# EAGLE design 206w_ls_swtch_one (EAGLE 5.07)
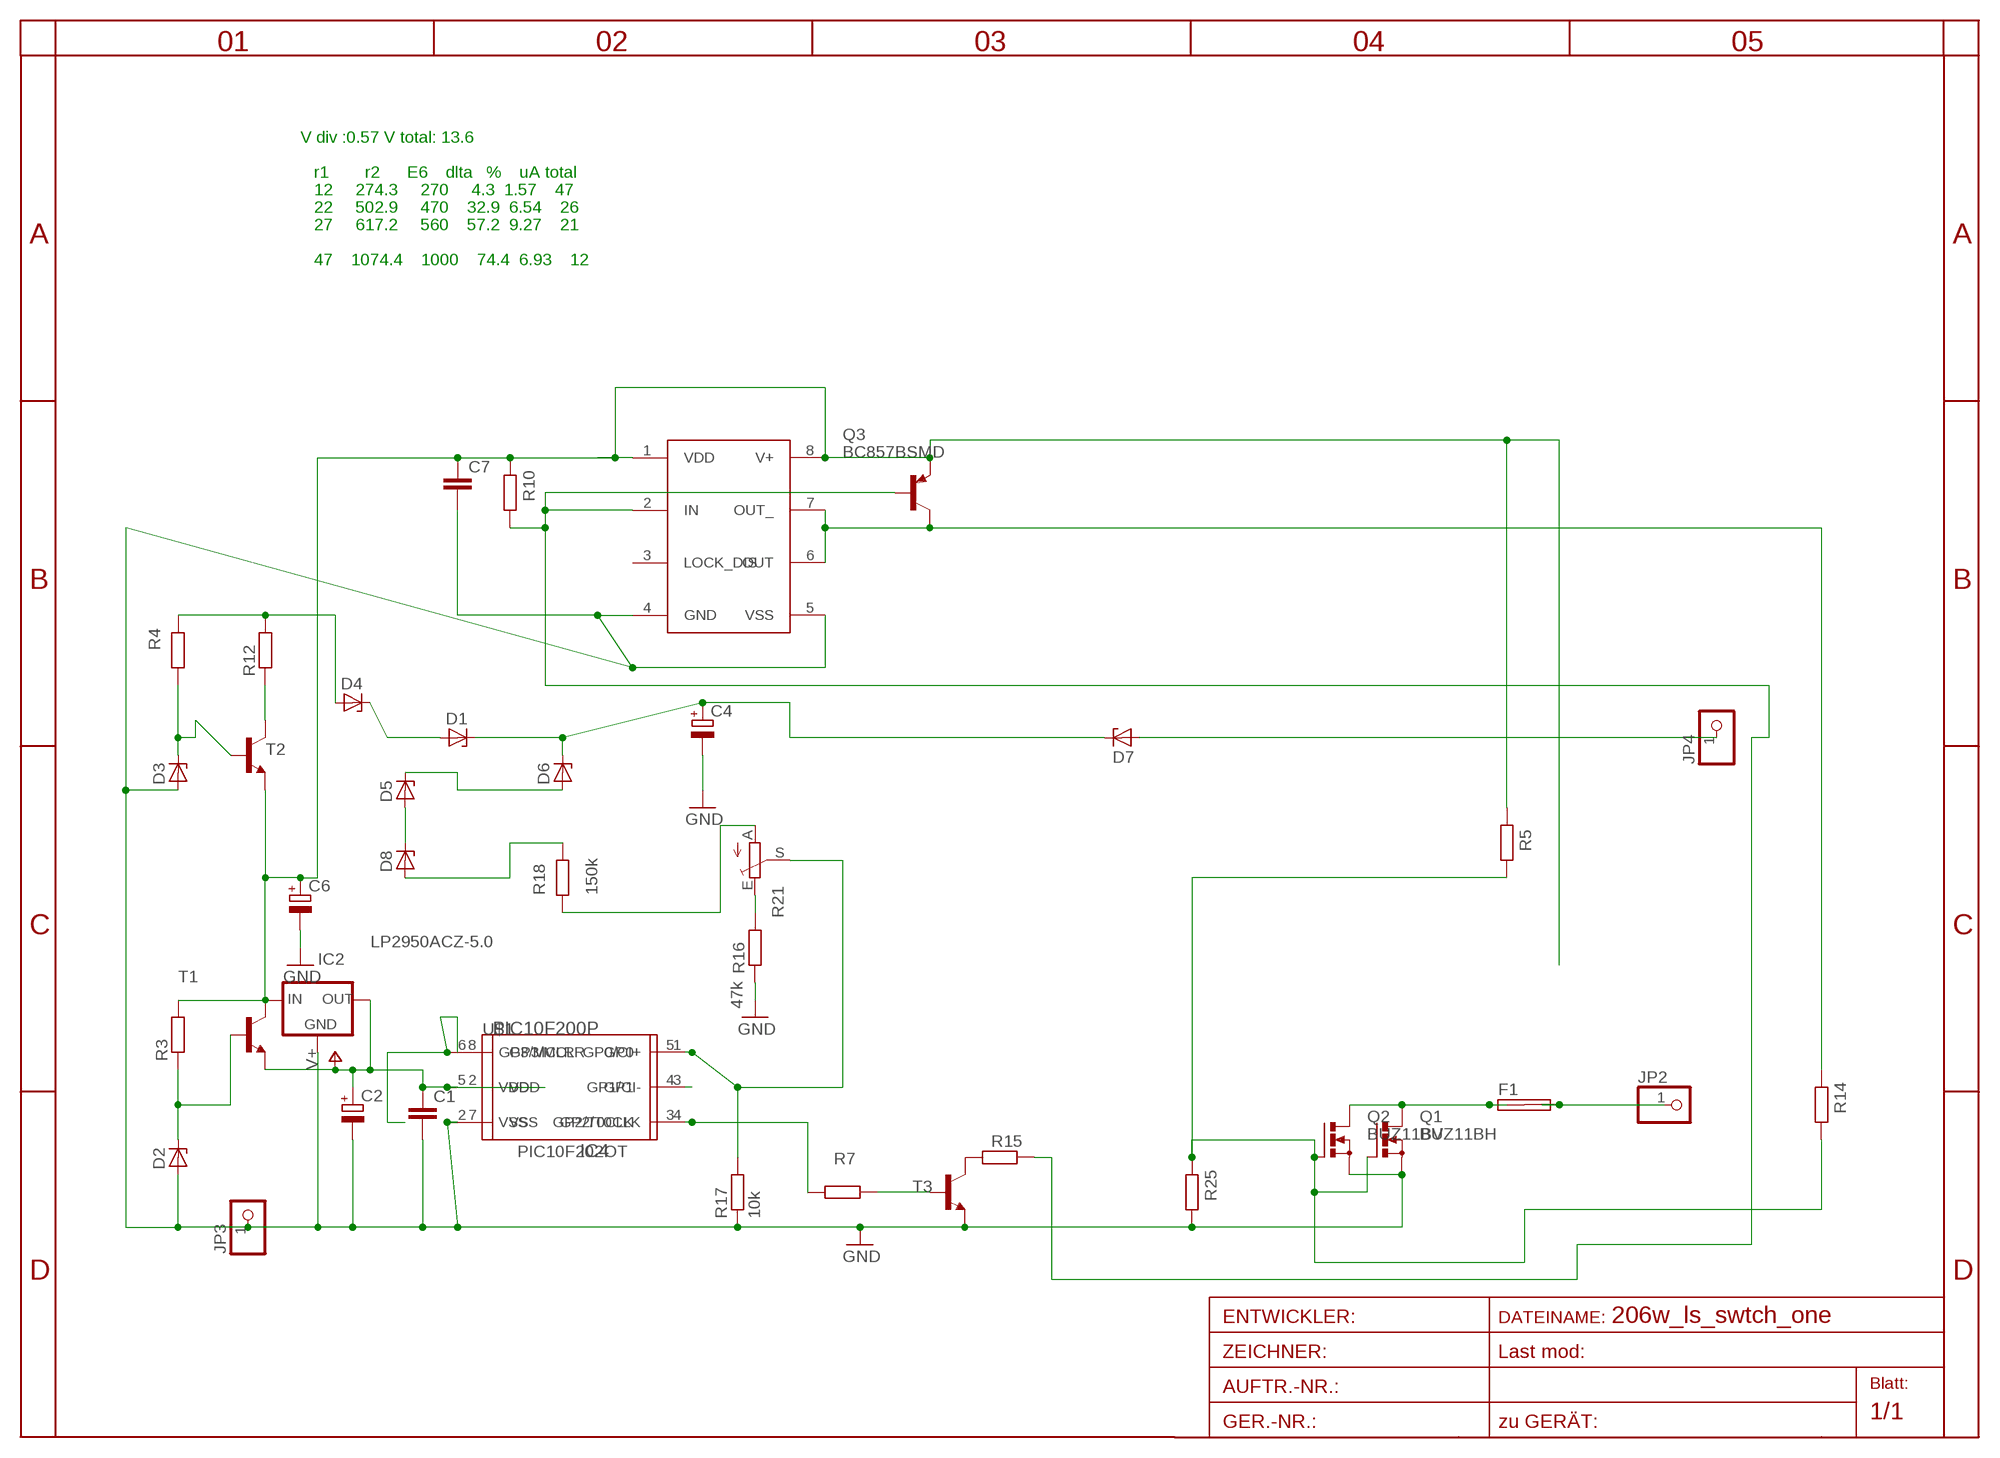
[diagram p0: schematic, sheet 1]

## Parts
C1  C-EUC1206  [C1206]
C2  CPOL-EUSANYO_SMD_E12  [SANYO-OSCON_SMD_E12]
C4  CPOL-EUE5-8.5  [E5-8,5]
C6  CPOL-EUSANYO_SMD_E12  [SANYO-OSCON_SMD_E12]
C7  C-EUC1206  [C1206]
D1  ZENER-DIODESMB  [SMB]
D2  ZENER-DIODESOD80C  [SOD80C]
D3  ZENER-DIODESMB  [SMB]
D4  ZENER-DIODESMB  [SMB]
D5  ZENER-DIODESMB  [SMB]
D6  ZENER-DIODESMB  [SMB]
D7  ZENER-DIODESMB  [SMB]
D8  ZENER-DIODESMB  [SMB]
F1  SHK20L7MM5  [7MM5]
IC2  LP2950ACZ-5.0  [TO92]
IC3  TC4432X  [SO-08]
IC4  PIC10F200P  [DIL8]
JP2  PINHD-1X11MM6  [1X1MM8]
JP3  PINHD-1X11MM6  [1X1MM8]
JP4  PINHD-1X11MM6  [1X1MM8]
Q1  BUZ11BH  [TO220BH]
Q2  BUZ11BV  [TO220BV]
Q3  BC857BSMD  [SOT23-BEC]
R3  R-EU_R0805  [R0805]
R4  R-EU_R0805  [R0805]
R5  R-EU_R0805  [R0805]
R7  R-EU_R0805  [R0805]
R10  R-EU_R0805  [R0805]
R12  R-EU_R0805  [R0805]
R14  R-EU_R0805  [R0805]
R15  R-EU_R0805  [R0805]
R16  47k  R-EU_R0805  [R0805]
R17  10k  R-EU_R0805  [R0805]
R18  150k  R-EU_R1206  [R1206]
R21  TRIM_EU-CA6V  [CA6V]
R25  R-EU_R0805  [R0805]
T1  BC846BLT1-NPN-SOT23-BEC  [SOT23-BEC]
T2  BC846BLT1-NPN-SOT23-BEC  [SOT23-BEC]
T3  BC846BLT1-NPN-SOT23-BEC  [SOT23-BEC]
U$1  PIC10F202OT  [SOT23-6]

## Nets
BB: IC3.2(IN) Q3.B R10.1 R15.2
GND: C1.2 C2.- C4.- C6.- C7.2 D2.A D3.A IC2.2(GND) IC3.4(GND) IC3.5(VSS) IC4.7(VSS) JP3.1 Q1.S Q2.S R16.1 R17.1 R25.1 T3.E U$1.2(VSS)
HOTSPOT: F1.1A F1.1B Q1.D Q2.D
N$1: IC4.5(GP0) R17.2 R21.S U$1.1(GP0/CI+)
N$2: IC4.8(GP3/MCLR) U$1.6(GP3/MCLR)
N$3: Q1.G Q2.G R5.1 R14.1 R25.2
N$4: R18.1 R21.A
N$5: R16.2 R21.E
N$6: D2.C R3.1 T1.B
N$7: D7.A JP4.1
N$9: IC4.3(GP2/T0CLK) R7.1 U$1.4(GP2/T0CLK)
N$10: D5.C D6.A
N$11: IC3.6(OUT) IC3.7(OUT_) Q3.C R14.2
N$12: D3.C R4.1 T2.B
N$16: R12.1 T2.C
N$17: D5.A D8.C
N$18: D1.A D4.C
N$19: D8.A R18.2
N$21: D4.A R4.2 R12.2
N$25: IC4.4(GP1) U$1.3(GP1/CI-)
N$26: R7.2 T3.B
N$31: R15.1 T3.C
OUT-: F1.2A F1.2B JP2.1
V60: C4.+ D1.C D6.C D7.C
V+: C1.1 C2.+ IC2.1(OUT) IC4.2(VDD) T1.E U$1.5(VDD)
VCC: C6.+ C7.1 IC2.3(IN) IC3.1(VDD) IC3.8(V+) Q3.E R3.2 R5.2 R10.2 T1.C T2.E
Unconnected: IC3.3(LOCK_DIS)

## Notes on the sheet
- V div :0.57 V total: 13.6
- r1        r2      E6    dlta   %    uA total
- 12     274.3     270     4.3  1.57    47
- 22     502.9     470    32.9  6.54    26
- 27     617.2     560    57.2  9.27    21
- 47    1074.4    1000    74.4  6.93    12

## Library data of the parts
C1 C7 = rcl:C-EU: CAPACITOR, European symbol
C2 C4 C6 = rcl:CPOL-EU: POLARIZED CAPACITOR, European symbol
D1-D8 = diode-1:ZENER-DIODE: Z-Diode
F1 = fuse:SHK20L: FUSE HOLDER 5 x 20 mm, SH contact, SHH1 Schukat, E1073 Buerklin
IC2 = v-reg:LP2950?*: Source: http://cache.national.com/ds/LP/LP2950.pdf
IC3 = microchip:TC4432
IC4 = microchip-5:PIC10F20*: uPC nW 0,25/0,5k Program Flash memory
JP2-JP4 = pinhead:PINHD-1X1: PIN HEADER
Q1 Q2 = transistor-power:BUZ11: N-CHANNEL MOS FET
Q3 = transistor-pnp:BC857*: PNP Transistror
R3-R5 R10 R12 R14-R16 R25 = rcl:R-EU_: RESISTOR, European symbol
R7 R17 R18 = rcl-2:R-EU_: RESISTOR, European symbol
R21 = pot:TRIM_EU-: POTENTIOMETER
T1-T3 = transistor-neu-to92:*-NPN-: NPN Transistror
U$1 = microchip-5:PIC10F2*: uPC nW 0,25/0,5k Program Flash memory Comparator

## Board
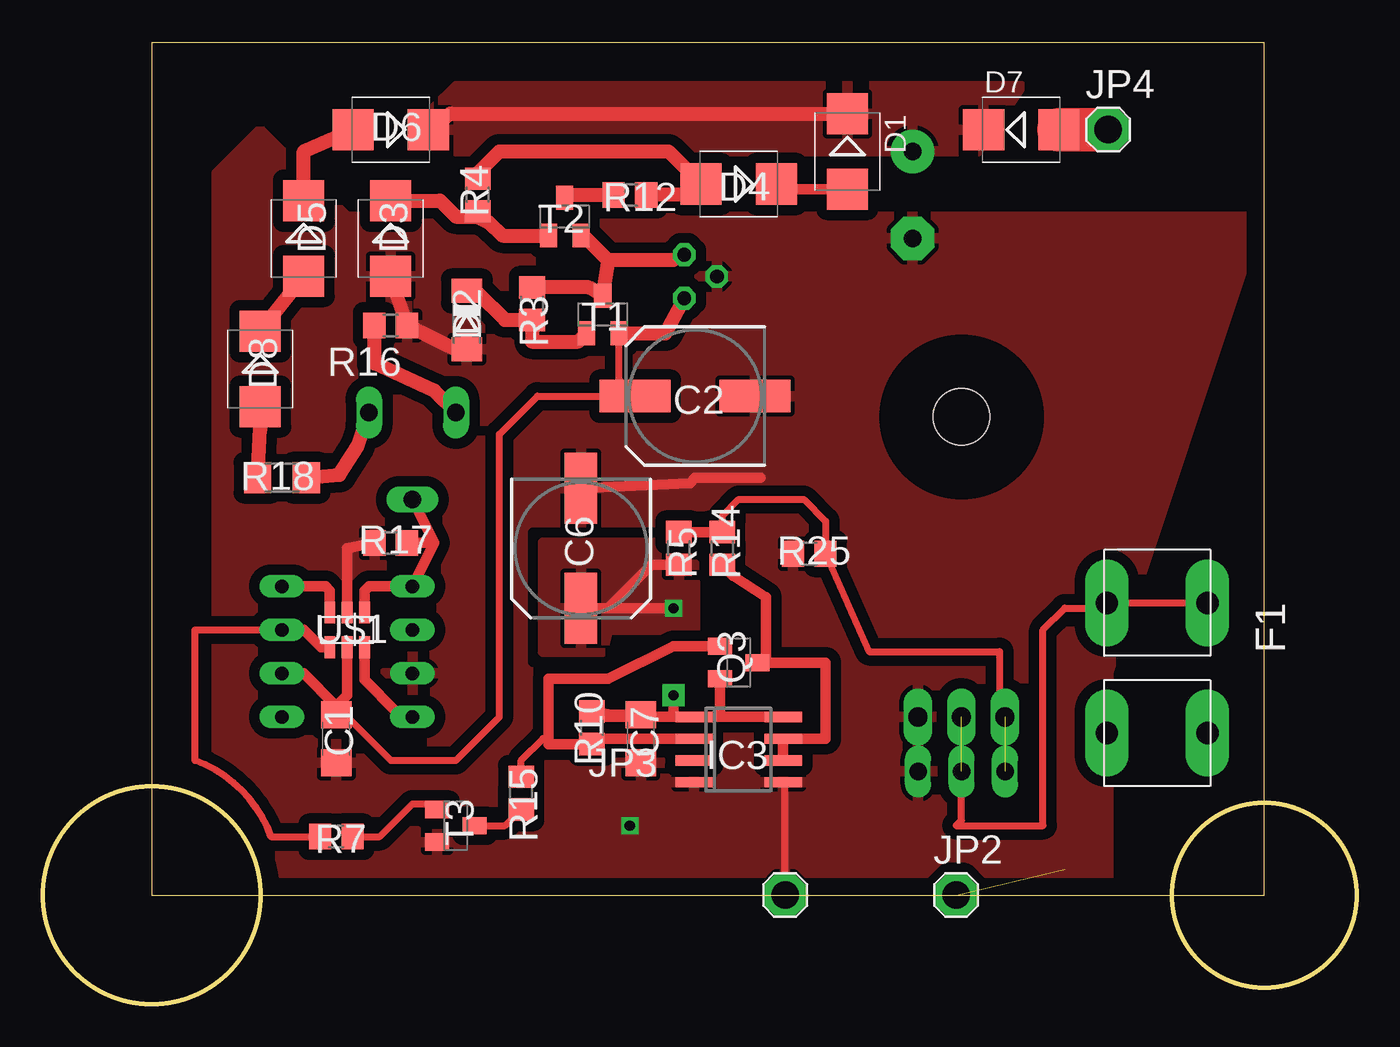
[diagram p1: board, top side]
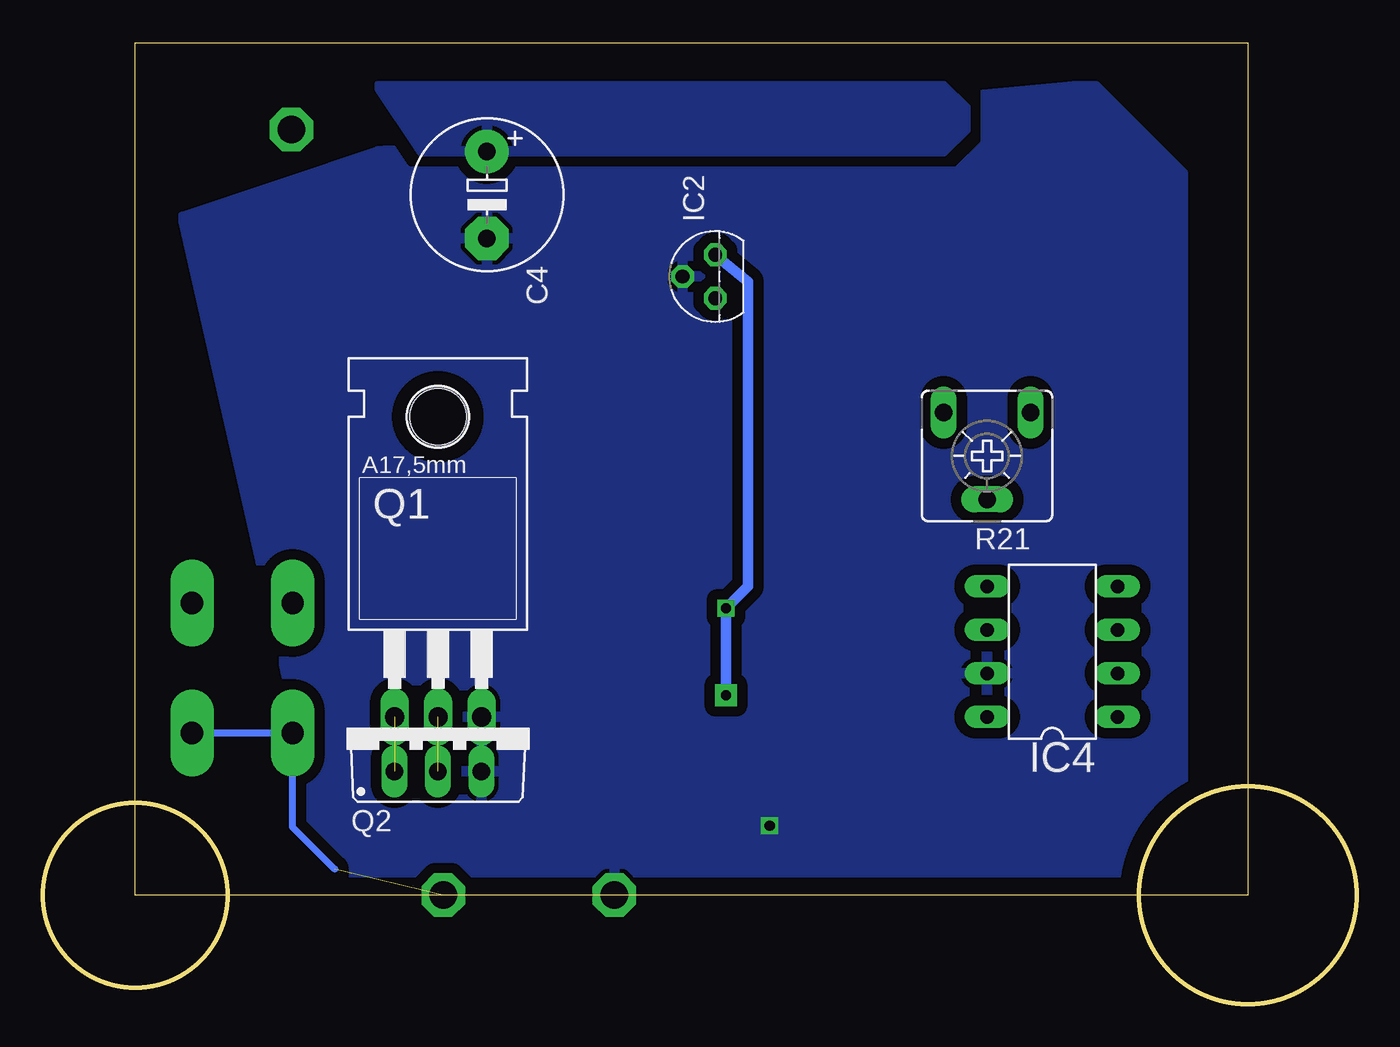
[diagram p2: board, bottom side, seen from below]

Size 76.74 x 56.11 mm. Coordinates in mm from the lower left corner, seen from the top.
Outline: 6.35,6.35 71.35,6.35 71.35,56.11 6.35,56.11 6.35,6.35
Outline: circle at 71.35,6.35 radius 5.39
Outline: circle at 6.35,6.35 radius 6.35
Copper layers (1*16): Top 0.035mm / dielectric 1.5mm / Bottom 0.035mm
Design rules "default": minimum track width 10mil, minimum drill 24mil, track to track 8mil, track to pad 8mil, pad to pad 8mil, via to via 8mil, smd to smd 8mil, copper to edge 40mil, drill to drill 8mil, minimum pad ring 10mil, minimum via ring 8mil, stop-mask expansion 4mil, vias tented up to drill 0mil, thermal gap 10mil

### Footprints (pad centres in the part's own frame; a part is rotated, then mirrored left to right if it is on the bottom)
C1206 = smd 1.6 x 1.8: 1 -1.4,0; 2 1.4,0
SANYO-OSCON_SMD_E12 = smd 4.15 x 1.9: + 3.5,0; - -3.5,0
E5-8,5 = drill 1.016 pad 2.54 round: + -2.54,0 | drill 1.016 pad 2.54 octagon: - 2.54,0
SMB = smd 2.4 x 2.4: A 2.2,0; C -2.2,0
SOD80C = smd 1.4 x 1.8: A 1.7,0; C -1.7,0
7MM5 = drill 1.3 pad 2.54 long: 1A -3.8,2.94; 1B -3.8,-2.94; 2A 3.8,2.94; 2B 3.8,-2.94
TO92 = drill 0.813 octagon: 1 -1.27,0; 2 0,1.905; 3 1.27,0
SO-08 = smd 0.6 x 2.2: 1 -1.905,-2.6; 2 -0.635,-2.6; 3 0.635,-2.6; 4 1.905,-2.6; 5 1.905,2.6; 6 0.635,2.6; 7 -0.635,2.6; 8 -1.905,2.6
DIL8 = drill 0.8 long: 1 -3.81,-3.81; 2 -1.27,-3.81; 3 1.27,-3.81; 4 3.81,-3.81; 5 3.81,3.81; 6 1.27,3.81; 7 -1.27,3.81; 8 -3.81,3.81
1X1MM8 = drill 1.6 pad 2.54 octagon: 1 0,0
TO220BH = drill 1.118 long: D 0,-6.35; G -2.54,-6.35; S 2.54,-6.35 | hole 3.302: 0,11.176
TO220BV = drill 1.016 long: D 0,-2.54; G -2.54,-2.54; S 2.54,-2.54
SOT23-BEC = smd 1 x 1.4: B -0.95,-1.1; C 0,1.1; E 0.95,-1.1
R0805 = smd 1.3 x 1.5: 1 -0.95,0; 2 0.95,0
R1206 = smd 1.6 x 1.803: 1 -1.422,0; 2 1.422,0
CA6V = drill 1.016 long: A -2.54,-2.54; E 2.54,-2.54; S 0,2.54
SOT23-6 = smd 0.635 x 1.27: 1 -1.016,-1.016; 2 0,-1.016; 3 1.016,-1.016; 4 1.016,1.016; 5 0,1.016; 6 -1.016,1.016

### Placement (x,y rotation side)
C1  17.14,15.48 270 top
C2  38.1,35.48 180 top
C4  50.8,47.23 270 bottom
C6  31.43,26.59 270 top
C7  34.92,15.48 270 top
D1  46.99,49.77 270 top
D2  24.77,39.93 270 top
D3  20.32,44.69 270 top
D4  40.64,47.87 180 top
D5  15.24,44.69 270 top
D6  20.32,51.04 180 top
D7  57.15,51.04 0 top
D8  12.7,37.07 270 top
F1  65.09,19.61 270 top
IC2  37.46,42.47 90 bottom
IC3  40.64,14.85 270 top
IC4  17.78,20.56 90 bottom
JP2  53.35,6.35 0 top
JP3  43.35,6.35 0 top
JP4  62.23,51.04 0 top
Q1  53.66,23.1 0 bottom
Q2  53.66,16.12 0 bottom
Q3  40.64,19.92 270 top
R3  28.58,40.88 90 top
R4  25.4,47.23 90 top
R5  37.15,26.59 270 top
R7  17.14,9.76 0 top
R10  32.07,16.12 90 top
R12  34.29,47.23 0 top
R14  39.69,26.59 270 top
R15  27.94,12.3 90 top
R16  20.32,39.61 180 top
R17  20.32,26.91 0 top
R18  13.97,30.72 180 top
R21  21.59,31.99 180 bottom
R25  44.77,26.27 0 top
T1  32.7,40.25 0 top
T2  30.48,45.96 0 top
T3  24.13,10.4 270 top
U$1  17.78,21.83 180 top

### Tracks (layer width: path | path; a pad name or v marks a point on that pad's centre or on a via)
BB
  Top 0.406: R15.2 27.94,14.21 29.21,15.48 29.53,15.48
  Top 0.61: Q3.B 36.83,20.88 33.02,18.97 29.53,18.97 29.53,15.48 29.53,15.16 R10.1 32.38,15.48 IC3.2
GND  (via drill 0.6)
  Top 0.406: JP3.1 43.35,12.83 IC3.5
  Top 0.61: C6.- 37.79,30.41 38.1,30.72 41.91,30.72 | U$1.2 17.78,26.59 R17.1
  Top 0.813: D3.A R16.1 24.56,38.02 D2.A
  other vias: 34.29,10.4
  pour Top (isolate 0.61, rank 3): 17.78,45.96 12.7,51.04 10.16,48.5 10.16,12.94 13.97,6.35 62.23,6.35 62.23,19.29 71.12,45.96
  pour Bottom (isolate 0.61, rank 3): 16.51,53.58 15.24,53.58 10.16,48.5 10.16,12.94 13.97,6.35 62.23,6.35 62.23,18.02 68.58,45.96 57.15,49.77
HOTSPOT  (1 unrouted)
  Top 0.406: Q2.D 53.66,10.72 53.34,10.4 58.42,10.4 58.42,21.83 59.69,23.1 61.84,23.1 F1.1B F1.1A
N$1
  Top 0.61: U$1.1 18.8,24.12 19.05,24.37 IC4.5 22.86,26.91 | 22.86,26.91 R21.S | 22.86,26.91 R17.2
N$2
  Top 0.61: U$1.6 18.8,18.91 20.64,17.07 21.27,17.07 IC4.8
N$3  (1 unrouted)
  Top 0.406: R14.1 39.69,28.5 40.64,29.45 44.45,29.45 45.72,28.18 R25.2 48.26,20.56 55.88,20.56 55.88,17.07 Q1.G
  Top 0.61: R5.1 R14.1
N$4
  Top 0.813: R18.1 17.31,30.88 18.41,32.62 R21.A
N$5
  Top 0.813: R16.2 19.37,37.39 22.86,35.8 R21.E
N$6
  Top 0.813: D2.C 24.88,41.52 25.4,41.52 26.98,39.93 R3.1 28.58,38.66 31.27,38.66 T1.B
N$7
  Top 2.54: D7.A JP4.1
N$9
  Top 0.406: R7.1 13.34,9.76 arc51 8.89,14.21 8.89,21.83 IC4.3
  Top 0.61: U$1.4 16.26,20.81 15.24,21.83 IC4.3
N$10
  Top 0.813: D6.A 15.24,49.77 D5.C
N$11
  Top 0.61: 42.23,19.92 Q3.C | 42.23,19.92 42.23,23.73 40.32,25.01 R14.2 | 42.23,19.92 45.72,19.92 45.72,15.48 IC3.7 IC3.6
N$12
  Top 0.813: D3.C 23.2,46.89 24.13,45.96 25.4,45.96 | T2.B 26.84,44.86 26.03,45.64 25.4,45.96 | 25.4,45.96 R4.1
N$16
  Top 0.813: R12.1 30.48,47.23 T2.C
N$17
  Top 0.813: D8.C D5.A
N$18
  Top 0.61: D1.A 43.13,47.57 D4.C
N$19
  Top 0.813: D8.A 12.7,33.58 R18.2
N$21
  Top 0.813: R4.2 25.4,48.5 26.67,49.77 36.53,49.77 D4.A 37.8,47.23 R12.2
N$25
  Top 0.61: U$1.3 16.76,24.12 16.51,24.37 IC4.4
N$26
  Top 0.406: R7.2 19.69,9.76 21.59,11.67 22.71,11.67 T3.B
N$31
  Top 0.406: T3.C 26.98,10.4 R15.1
OUT-  (1 unrouted)
  Bottom 0.406: F1.2A F1.2B 62.15,10.32 59.69,7.86
V60
  Top 0.813: D1.C 23.79,51.97 D6.C
  pour Top (isolate 0.61): 57.15,53.58 24.13,53.58 22.86,52.31 22.86,51.04 24.13,49.77 54.61,49.77
  pour Bottom (isolate 0.61): 57.15,53.58 24.13,53.58 22.86,52.31 22.86,51.04 24.13,49.77 54.61,49.77
V+
  Top 0.406: T1.E 33.65,36.44 34.29,35.8 34.29,35.79 C2.+ 28.89,35.48 26.67,33.26 26.67,16.75 24.13,14.21 20.32,14.21 17.78,16.75 17.27,16.75 C1.1
  Top 0.61: 17.14,17.38 C1.1 | 17.14,17.38 15.24,19.29 IC4.2 | U$1.5 17.78,18.02 17.14,17.38
  Top 0.813: T1.E 36.37,39.15 IC2.1
VCC  (via drill 0.6, 0.6 pad 1.27)
  Top 0.61: Q3.E 39.54,16.9 39.69,16.75 | 41.27,16.75 IC3.8 39.69,16.75 | 39.69,16.75 IC3.1 36.83,16.75 | 36.83,16.75 31.88,16.75 C7.1 33.2,16.88 R10.2 | R5.2 35.56,25.64 33.02,23.1 | 32.06,23.1 C6.+ 31.75,23.1 32.06,23.1 | v36.83,23.1 33.02,23.1 | 36.83,16.75 v36.83,18.02 | 33.02,23.1 32.06,23.1 | IC2.3 36.83,43.42
  Top 0.813: T2.E 31.58,44.86 33.02,43.42 | 33.02,43.42 T1.C 31.9,41.83 R3.2 | 36.83,43.42 33.02,43.42
  Bottom 0.61: v36.83,18.02 v36.83,23.1 35.56,24.37 35.56,42.15 IC2.3
  pour Top (isolate 0.61): 29.21,26.91 36.83,26.91 38.1,25.64 38.1,21.83 33.02,21.83 32.7,20.56 29.21,20.56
